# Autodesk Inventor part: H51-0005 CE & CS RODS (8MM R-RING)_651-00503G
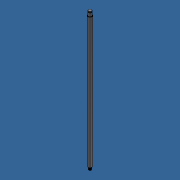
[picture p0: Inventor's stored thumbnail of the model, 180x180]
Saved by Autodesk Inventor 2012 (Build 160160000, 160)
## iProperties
Created: 2013-10
Part Number: H51-0005 CE & CS RODS (8MM R-RING)_651-00503G
Material: Steel
Document SubType Name: Modeling
Designer: Admin
Density: 7.85 g/cm^3
Mass: 202.212 g
Surface Area: 105.768 cm^2
Volume: 25.7594 cm^3
Author: Admin
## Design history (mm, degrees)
node "H51-0005 CE & CS RODS (8MM R-RING)_651-00503G1"
node "Base1"
body "Solid1"
